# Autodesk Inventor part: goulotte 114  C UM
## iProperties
Shininess: 20.0
Angle Display Precision: 2
Document Length Units: 11269
Document Angle Units: 11279
Document Time Units: 11290
Document Mass Units: 11283
Document Length Units Precision: 3
Document Angle Units Precision: 2
Created: 2002-02
Part Number: goulotte 114  C UM
Material: Par défaut
Catalog Web Link: www.traceparts.com
Description: Cornière à ailes égales et à coins arrondis 20 mm x3 mm x 0.200 m - NF A 45-009
Document SubType Name: Modélisation
Designer: Administrateur
Density: 0.0
Volumn: 0.0
Area: 0.0
PropertySet Name: Model Information
Control State: 0
Master: False
Checked Out: False
Author: Administrateur
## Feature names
1. Extrusion1
2. Extrusion2
3. Perçage1 [Hole]
4. Base1
